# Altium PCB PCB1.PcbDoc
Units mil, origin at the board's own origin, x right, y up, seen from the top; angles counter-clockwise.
Board outline 6000 x 4000 mil, 2 copper layers (Top Layer, Bottom Layer); 4 components, 34 nets, 45 pads, 12 vias.
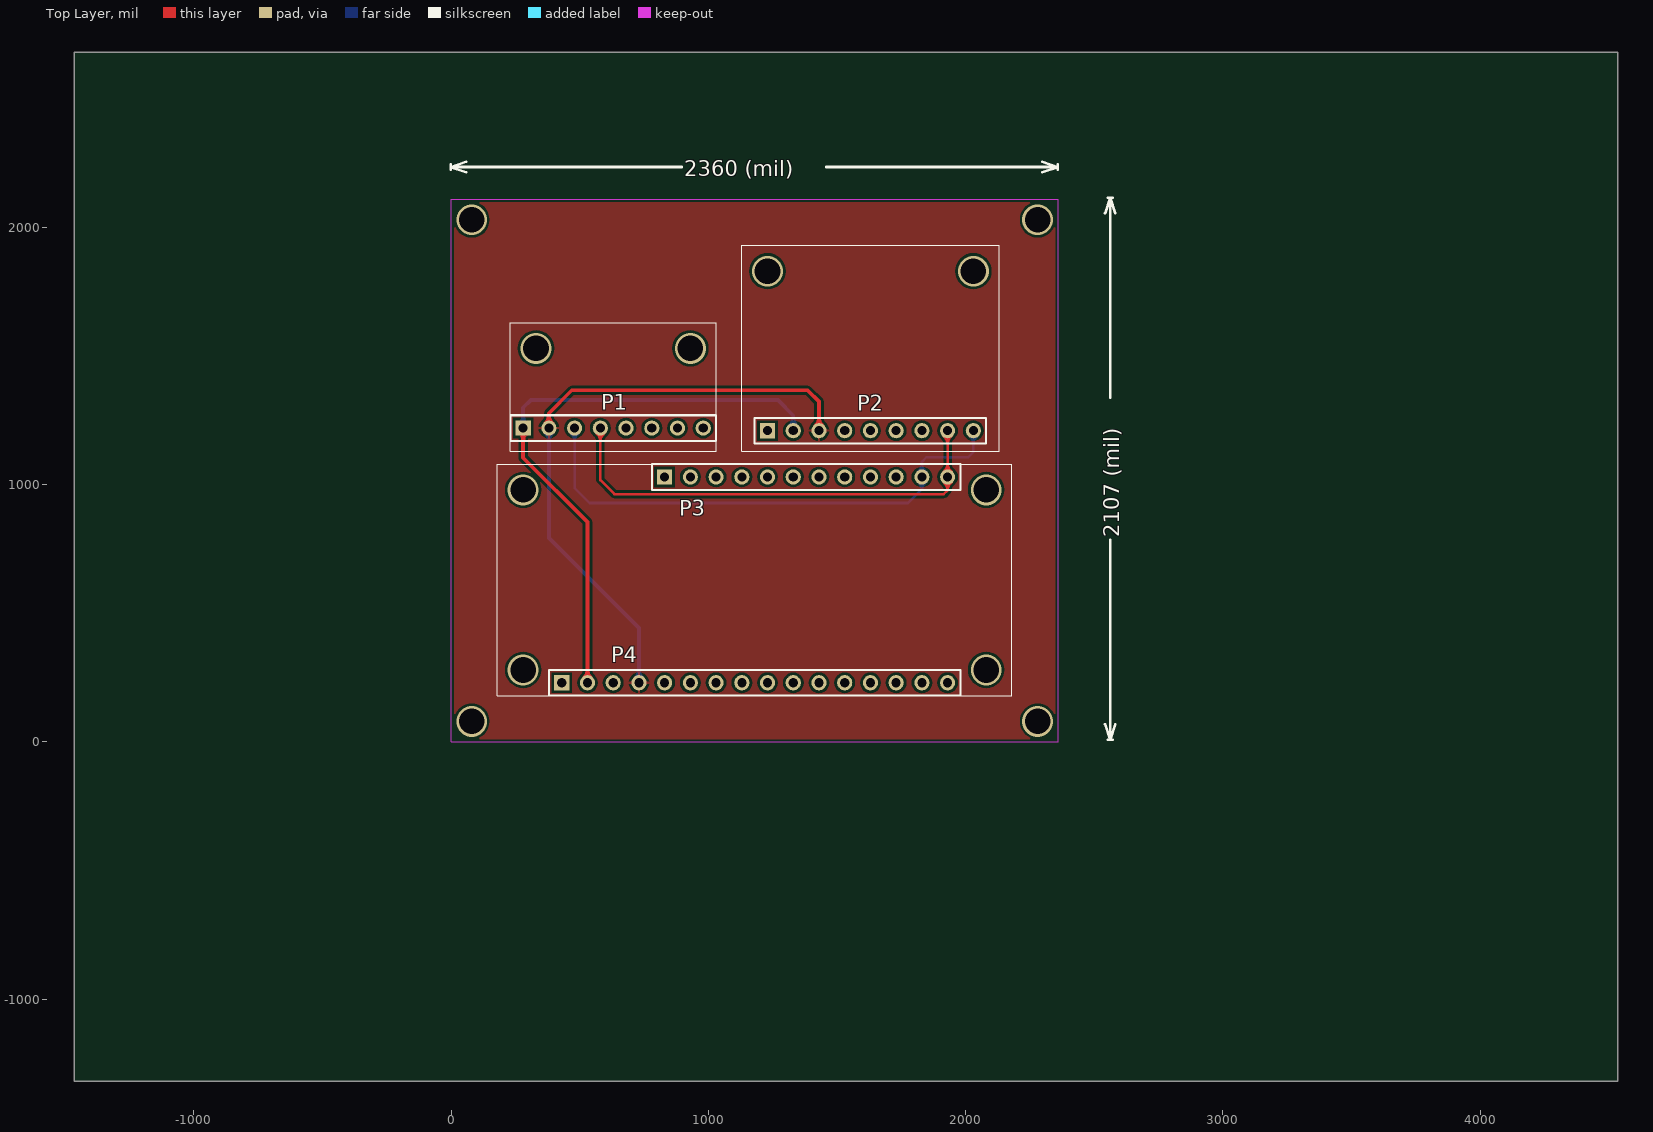
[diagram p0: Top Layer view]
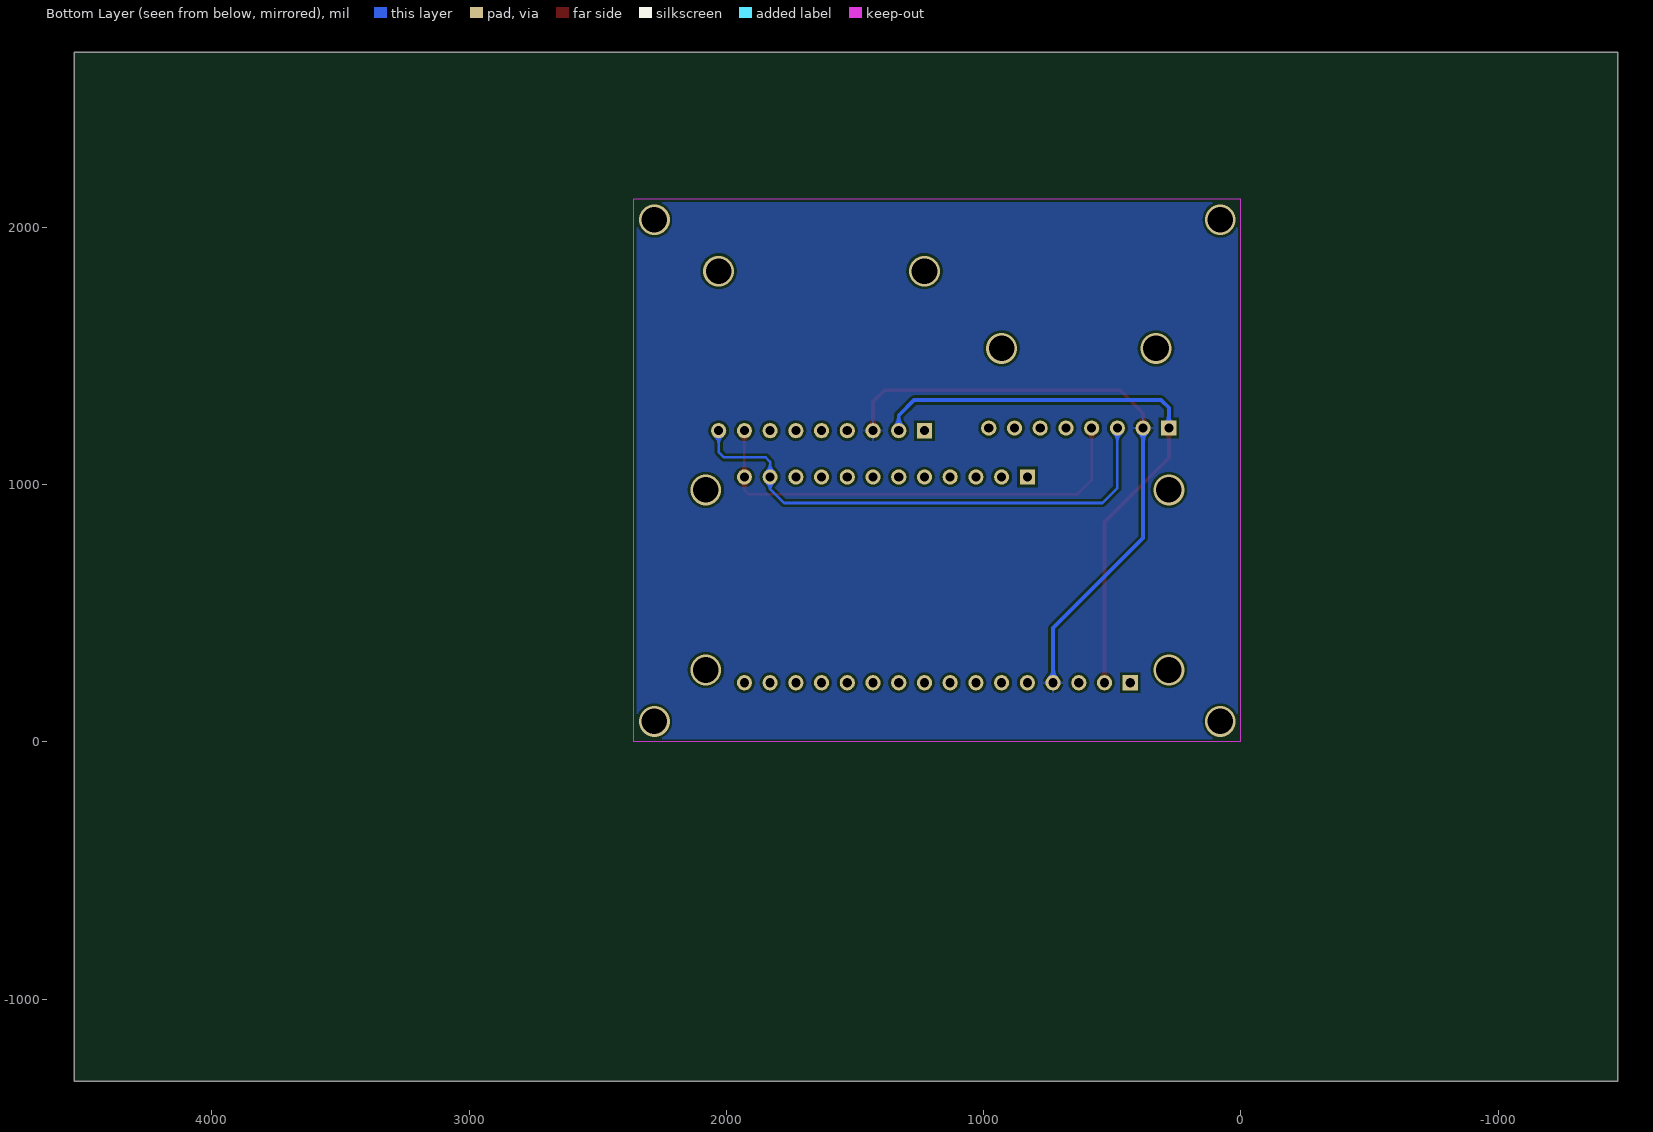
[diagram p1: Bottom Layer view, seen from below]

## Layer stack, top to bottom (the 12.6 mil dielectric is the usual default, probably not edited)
Top Solder: solder mask 0.4, Solder Resist, Dk 3.5
Top Layer: signal copper 1.4
Dielectric 1: dielectric 12.6, FR-4, Dk 4.8
Bottom Layer: signal copper 1.4
Bottom Solder: solder mask 0.4, Solder Resist, Dk 3.5

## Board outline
-1465,-1319 4535,-1319 4535,2681 -1465,2681

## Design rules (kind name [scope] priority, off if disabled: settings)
Clearance [All] p1: gap=10 ignorepadtopadclearanceinfootprint=FALSE except(0: Arc-Hole Track-Hole SMDPad-Hole THPad-Hole Via-Hole Fill-Hole Poly-Hole Region-Hole Text-Hole)
PolygonConnect [All] p1: connectstyle=Relief reliefconductorwidth=10 reliefentries=4 polygonreliefangle="90 Angle" airgapwidth=10
RoutingVias [All] p1: holewidth=28 width=50 viastyle="Through Hole" minholewidth=28 minwidth=50 maxholewidth=28 maxwidth=50
SolderMaskExpansion [All] p1: expansion=4
Width [All] p1: maxlimit=20 minlimit=10 preferedwidth=10
30 further rules are at their usual default settings.

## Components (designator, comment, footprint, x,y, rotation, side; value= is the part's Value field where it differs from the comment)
P1 "Header 8" HDR1X8 280,1220 r0 top
P2 "Header 9" HDR1X9 1230,1210 r0 top
P3 "Header 12" HDR1X12 830,1030 r0 top
P4 "Header 16" HDR1X16 430,230 r0 top

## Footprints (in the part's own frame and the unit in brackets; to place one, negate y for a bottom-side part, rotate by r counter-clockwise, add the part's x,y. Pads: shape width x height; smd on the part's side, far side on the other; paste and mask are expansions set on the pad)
HDR1X8 [mm] "Connector; Header; 8 Position"
  rect 1.5x1.5 hole 0.9: 1(0,0)
  round 1.5 hole 0.9: 2(2.54,0) 3(5.08,0) 4(7.62,0) 5(10.16,0) 6(12.7,0) 7(15.24,0) 8(17.78,0)
  silkscreen extent -1.27,-1.27 19.05,1.27
HDR1X9 [mm] "Connector; Header; 9 Position"
  rect 1.5x1.5 hole 0.9: 1(0,0)
  round 1.5 hole 0.9: 2(2.54,0) 3(5.08,0) 4(7.62,0) 5(10.16,0) 6(12.7,0) 7(15.24,0) 8(17.78,0) 9(20.32,0)
  silkscreen extent -1.27,-1.27 21.59,1.27
HDR1X12 [mm] "Connector; Header; 12 Position"
  rect 1.5x1.5 hole 0.9: 1(0,0)
  round 1.5 hole 0.9: 2(2.54,0) 3(5.08,0) 4(7.62,0) 5(10.16,0) 6(12.7,0) 7(15.24,0) 8(17.78,0) 9(20.32,0) 10(22.86,0) 11(25.4,0) 12(27.94,0)
  silkscreen extent -1.27,-1.27 29.21,1.27
HDR1X16 [mm] "Connector; Header; 16 Position"
  rect 1.5x1.5 hole 0.9: 1(0,0)
  round 1.5 hole 0.9: 2(2.54,0) 3(5.08,0) 4(7.62,0) 5(10.16,0) 6(12.7,0) 7(15.24,0) 8(17.78,0) 9(20.32,0) 10(22.86,0) 11(25.4,0) 12(27.94,0) 13(30.48,0) 14(33.02,0) 15(35.56,0) 16(38.1,0)
  silkscreen extent -1.27,-1.27 39.37,1.27

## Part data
P1: "Header, 8-Pin"
P2: "Header, 9-Pin"
P3: "Header, 12-Pin"
P4: "Header, 16-Pin"

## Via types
v1: diameter 120, hole 100, Top Layer to Bottom Layer, 12 vias

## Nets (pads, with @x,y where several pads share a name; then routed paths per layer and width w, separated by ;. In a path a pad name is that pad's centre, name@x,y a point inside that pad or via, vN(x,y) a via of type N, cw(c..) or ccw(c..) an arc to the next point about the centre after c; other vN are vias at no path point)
3V3: P1.1 P2.2 P4.2 | length 2318.8
  Top Layer w15: P1.1 280,1105 530,855 P4.2
  Bottom Layer w15: P1.1 280,1299 310,1329 1270,1329 1330,1269 P2.2
6: P3.9
9~: P3.8
11: P3.6
12: P3.5
13: P3.4
A0: P4.5
A1: P4.6
A2: P4.7
A3: P4.8
A4-: P4.9
A5-: P4.10
ALERT: P1.5
ARF: P4.3
BAT: P3.1
CS: P2.4
DFU: P4.16
EN: P3.2
GND: P1.2 P2.3 P4.4 | length 2411.1
  Top Layer w15: P1.2 380,1278 469,1367 1386,1367 1430,1323 P2.3
  Bottom Layer w15: P1.2 380,793 730,443 P4.4
INT1: P2.5
INT2: P2.6
MISO: P4.13
MOSI: P4.12
RST: P4.1
RX: P4.14
SCK: P4.11
SCL: P1.3 P2.9 P3.11 | length 2034.1
  Bottom Layer w10: P1.3 480,987 538,929 1776,929 1830,983 P3.11 1830,1089 1847,1106 2009,1106 2030,1127 P2.9
SDA: P1.4 P2.8 P3.12 | length 1813
  Top Layer w10: P1.4 580,1018 635,963 1915,963 1930,978 P3.12 P2.8
SDO: P2.7
TX: P4.15
USB: P3.3
VIN: P2.1
~5: P3.10
~10: P3.7
pads on no net: P1.6 P1.7 P1.8
copper on no net:
  other v1: 80,80 2280,80 280,280 2080,280 280,980 2080,980 330,1530 930,1530 1230,1830 2030,1830 80,2030 2280,2030

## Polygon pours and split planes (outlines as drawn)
GND on Top Layer "Top Layer-No Net" (solid, remove dead copper, pour order 0): 0,2110 0,0 2360,0 2360,2110
GND on Bottom Layer "Top Layer-No Net" (solid, remove dead copper, pour order 3): 0,2110 0,0 2360,0 2360,2110

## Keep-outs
Keep-Out Layer:
  lines w2: 0,0 2360,0 2360,2110 0,2110 0,0

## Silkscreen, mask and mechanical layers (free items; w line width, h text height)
Top Overlay:
  lines w2: 180,180 2180,180 2180,1080 180,1080 180,180 ; 230,1130 1030,1130 1030,1630 230,1630 230,1130 ; 1130,1130 2130,1130 2130,1930 1130,1930 1130,1130
  lines w10: -2.09,2225 -2.09,2245 ; 57.91,2215 -2.09,2235 ; 57.91,2255 -2.09,2235 ; 897,2235 -2.09,2235 ; 1458.83,2235 2357.91,2235 ; 2297.91,2215 2357.91,2235 ; 2297.91,2255 2357.91,2235 ; 2357.91,2225 2357.91,2245 ; 2542,68.42 2562,8.42 ; 2542,2055.42 2562,2115.42 ; 2552,8.42 2572,8.42 ; 2552,2115.42 2572,2115.42 ; 2562,786 2562,8.42 ; 2562,1337.83 2562,2115.42 ; 2582,68.42 2562,8.42 ; 2582,2055.42 2562,2115.42
  text "2360 (mil)" at 907,2199.01 h60
  text "2107 (mil)" at 2597.99,796 h60 r90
